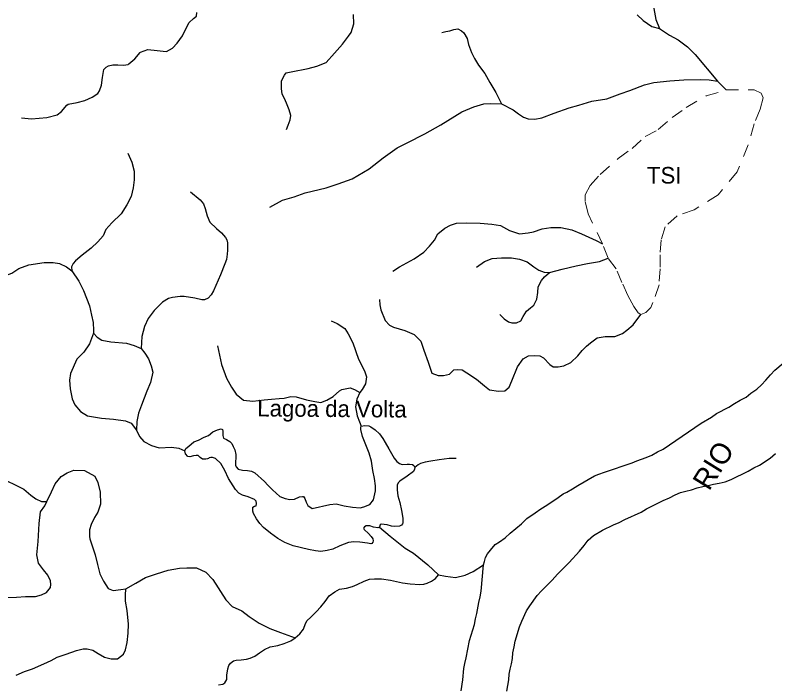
# Model space of a CAD drawing. Extents: x 436.3 to 500.4, y 8231 to 8286.4.
# Drawn here: x 478.01 to 485.33, y 8235.53 to 8241.98 of the extents above; entities that cross this region are included whole.
import ezdxf
from ezdxf.enums import TextEntityAlignment as Align

# ---------------------------------------------------------------- set-up
doc = ezdxf.new("R2010")
doc.units = 0
doc.header["$LTSCALE"] = 0.08
doc.linetypes.add('LONG_DASHED', pattern=[7.5, 6, -1.5])
doc.linetypes.add('SHORT_DASHED', pattern=[2.7, 1.5, -1.2])
for name, color, linetype, lineweight in [('2', 7, 'Continuous', 25), ('21', 7, 'SHORT_DASHED', 13), ('9', 7, 'LONG_DASHED', 25)]:
    doc.layers.add(name, color=color, linetype=linetype, lineweight=lineweight)
doc.layers.add('61', color=7, linetype='Continuous')

msp = doc.modelspace()

# ---------------------------------------------------------------- linework, layer by layer
at = {"layer": '2'}
msp.add_line((482.4993, 8236.4278), (482.5205, 8236.6809), dxfattribs=at)
for points in [[(482.5585, 8236.7874), (482.5884, 8236.8242), (482.6352, 8236.8765), (482.6757, 8236.9034), (482.7298, 8236.9437), (482.7794, 8236.9886), (482.8876, 8237.0783), (482.9373, 8237.1276), (483.0185, 8237.1814), (483.0726, 8237.2218), (483.1312, 8237.2577), (483.2395, 8237.3294), (483.2892, 8237.3653), (483.3252, 8237.3833), (483.3794, 8237.4146), (483.4291, 8237.446), (483.5916, 8237.5402), (483.6322, 8237.5537), (483.6863, 8237.5761), (483.9526, 8237.6657), (483.9978, 8237.6837), (484.0892, 8237.7158), (484.1423, 8237.7374), (484.1965, 8237.7688), (484.2508, 8237.7957), (484.6172, 8238.0473), (484.7168, 8238.1052), (484.7666, 8238.1411), (484.8842, 8238.1994), (484.9385, 8238.2353), (484.9928, 8238.2667), (485.0516, 8238.2981), (485.0969, 8238.3339), (485.1558, 8238.3743), (485.2011, 8238.4147), (485.2419, 8238.4596), (485.2872, 8238.5134), (485.328, 8238.5583), (485.4095, 8238.6256)], [(479.6433, 8237.7815), (479.6539, 8237.8026), (479.6832, 8237.8264), (479.7285, 8237.8659), (479.7736, 8237.8842), (479.8294, 8237.9105), (479.872, 8237.929), (479.9145, 8237.9631), (479.9571, 8237.9816), (479.9943, 8237.9921), (480.0075, 8237.9868), (480.0102, 8237.9682), (480.0082, 8237.9546), (480.0082, 8237.9415), (480.0105, 8237.9291), (480.0167, 8237.9006), (480.0444, 8237.8889), (480.0762, 8237.8704), (480.0947, 8237.8519), (480.1105, 8237.8228), (480.1237, 8237.791), (480.1342, 8237.7461), (480.1319, 8237.6433), (480.1372, 8237.6275), (480.1584, 8237.6036), (480.1981, 8237.593), (480.2485, 8237.5903), (480.2856, 8237.5849), (480.3175, 8237.569), (480.4108, 8237.4844), (480.4422, 8237.4485), (480.487, 8237.4036), (480.5588, 8237.3407), (480.6113, 8237.3202), (480.6536, 8237.3122), (480.7014, 8237.3147), (480.7491, 8237.3358), (480.7757, 8237.341), (480.7863, 8237.341), (480.7996, 8237.3199), (480.8127, 8237.2855), (480.8285, 8237.255), (480.8689, 8237.2236), (481.0399, 8237.2637), (481.1028, 8237.2681), (481.1792, 8237.2501), (481.2601, 8237.2365), (481.3321, 8237.232), (481.3681, 8237.2409), (481.4266, 8237.2633), (481.4627, 8237.3081), (481.4809, 8237.3933), (481.4811, 8237.4427), (481.4723, 8237.5145), (481.4545, 8237.5907), (481.4413, 8237.6805), (481.4191, 8237.7568), (481.3566, 8237.9183), (481.3408, 8237.9847), (481.3382, 8238.0031), (481.3435, 8238.019)], [(481.3435, 8238.019), (481.378, 8238.0242), (481.4178, 8238.0216), (481.4363, 8238.011), (481.4787, 8237.9819), (481.5184, 8237.9422), (481.55, 8237.8999), (481.5738, 8237.8603), (481.608, 8237.7994), (481.6608, 8237.7095), (481.6872, 8237.6778), (481.711, 8237.6592), (481.7375, 8237.6487), (481.7852, 8237.6513), (481.8091, 8237.6513), (481.8383, 8237.6486), (481.8515, 8237.638), (481.8594, 8237.6195)], [(481.4617, 8237.0442), (481.4272, 8237.0575), (481.3901, 8237.0575), (481.3742, 8237.0496), (481.3661, 8237.0364), (481.3714, 8237.0232), (481.4138, 8236.9834), (481.4402, 8236.9544), (481.456, 8236.9332), (481.4586, 8236.9121), (481.4559, 8236.8989), (481.4453, 8236.8883), (481.4347, 8236.8857), (481.4029, 8236.891), (481.3312, 8236.9), (481.2728, 8236.9046), (481.2188, 8236.8957), (481.1378, 8236.8644), (481.0703, 8236.8331), (481.0163, 8236.8197), (480.9533, 8236.8108), (480.9038, 8236.8154), (480.8364, 8236.8289), (480.6881, 8236.8651), (480.6072, 8236.8966), (480.5398, 8236.9371), (480.468, 8236.9865), (480.4006, 8237.0405), (480.3647, 8237.0809), (480.3333, 8237.1258), (480.3065, 8237.1752), (480.2971, 8237.1991), (480.2972, 8237.2255), (480.2999, 8237.236), (480.3159, 8237.2465), (480.3292, 8237.2518), (480.3345, 8237.2729), (480.3293, 8237.2941), (480.316, 8237.3099), (480.2551, 8237.3365), (480.1994, 8237.3524), (480.1623, 8237.371), (480.1305, 8237.4081), (480.0645, 8237.5138), (480.0276, 8237.5905), (479.9906, 8237.6593), (479.9377, 8237.7069), (479.9112, 8237.7149), (479.8926, 8237.715), (479.8767, 8237.7123), (479.8713, 8237.7071), (479.8633, 8237.7018), (479.8447, 8237.6992), (479.8129, 8237.6993), (479.7917, 8237.7152), (479.7705, 8237.7337), (479.752, 8237.7364), (479.7281, 8237.7312), (479.6908, 8237.7207), (479.6723, 8237.7261), (479.6485, 8237.7498), (479.6433, 8237.7815)], [(484.6331, 8237.4362), (484.6873, 8237.4452), (484.7371, 8237.4586), (484.7913, 8237.4675), (484.85, 8237.4809), (484.9088, 8237.5033), (485.0717, 8237.584), (485.126, 8237.6154), (485.1803, 8237.6423), (485.2845, 8237.7095), (485.3343, 8237.7544)], [(481.8594, 8237.6195), (481.8566, 8237.6036), (481.846, 8237.5825), (481.7871, 8237.5366), (481.715, 8237.4873), (481.6988, 8237.4721), (481.6881, 8237.4484), (481.688, 8237.4034), (481.6958, 8237.3453), (481.7142, 8237.2818), (481.7322, 8237.2047), (481.7455, 8237.1329), (481.7453, 8237.088), (481.7401, 8237.0783), (481.7295, 8237.0651), (481.7109, 8237.0545), (481.6684, 8237.052), (481.634, 8237.0546)], [(484.3123, 8237.3288), (484.3665, 8237.3557), (484.4207, 8237.3781), (484.4704, 8237.3915), (484.5247, 8237.4049), (484.5789, 8237.4228), (484.6331, 8237.4362)], [(482.746, 8235.4671), (482.764, 8235.5748), (482.7684, 8235.6287), (482.7774, 8235.678), (482.7909, 8235.7274), (482.7999, 8235.7813), (482.8044, 8235.8351), (482.818, 8235.8935), (482.827, 8235.9473), (482.8696, 8236.0843), (482.8901, 8236.1403), (482.9352, 8236.239), (482.9668, 8236.2884), (483.0389, 8236.387), (483.0795, 8236.4319), (483.1832, 8236.5351), (483.2328, 8236.5934), (483.3457, 8236.7055), (483.445, 8236.8132), (483.4902, 8236.867), (483.5309, 8236.9208), (483.5821, 8236.9651), (483.6663, 8237.015), (483.7747, 8237.0688), (483.8288, 8237.0912), (483.883, 8237.1181), (484.0409, 8237.1882), (484.0908, 8237.2212), (484.2535, 8237.3019), (484.3123, 8237.3288)], [(481.5199, 8237.0441), (481.504, 8237.0389), (481.4617, 8237.0442)], [(481.634, 8237.0546), (481.5942, 8237.0679), (481.536, 8237.0732), (481.5253, 8237.068), (481.5199, 8237.0441)], [(482.5205, 8236.6809), (482.5304, 8236.7134), (482.5306, 8236.7141), (482.5399, 8236.7531), (482.5585, 8236.7874)], [(482.3052, 8235.4675), (482.3232, 8235.5752), (482.3322, 8235.6829), (482.3412, 8235.7323), (482.3547, 8235.7861), (482.3872, 8235.9538), (482.4357, 8236.1076), (482.4449, 8236.163), (482.4585, 8236.2124), (482.4766, 8236.3201), (482.4902, 8236.3739), (482.4993, 8236.4278)]]:
    msp.add_lwpolyline(points, dxfattribs=at)
at = {"layer": '21'}
msp.add_line((483.7228, 8239.6353), (483.6676, 8239.7737), dxfattribs=at)
for points in [[(483.6676, 8239.7737), (483.5291, 8240.0628), (483.5003, 8240.1878), (483.5003, 8240.2455), (483.5485, 8240.3349), (483.6449, 8240.4407), (483.8183, 8240.5947), (483.9532, 8240.6908), (484.0785, 8240.8063), (484.2038, 8240.8737), (484.3387, 8240.989), (484.4735, 8241.0853), (484.6664, 8241.1979), (484.8593, 8241.2554)], [(484.8593, 8241.2554), (485.0716, 8241.255), (485.1295, 8241.2549), (485.1971, 8241.2259), (485.2164, 8241.1778), (485.1876, 8241.0718), (485.1298, 8240.9275), (485.072, 8240.7254), (484.9659, 8240.4657), (484.7825, 8240.2447), (484.5509, 8240.1007), (484.3868, 8240.0432), (484.271, 8239.9375), (484.2323, 8239.8125), (484.2224, 8239.6683), (484.2222, 8239.5338), (484.2123, 8239.38), (484.1541, 8239.2072), (484.1347, 8239.1592), (484.0864, 8239.1113), (484.0381, 8239.092)], [(484.0381, 8239.092), (484.0114, 8239.1076), (483.9708, 8239.1689), (483.9133, 8239.2746), (483.8557, 8239.3995), (483.7982, 8239.534), (483.7228, 8239.6353)]]:
    msp.add_lwpolyline(points, dxfattribs=at)
at = {"layer": '9'}
for points in [[(484.1215, 8242.3853), (484.1999, 8242.3364), (484.2104, 8242.2515), (484.1765, 8242.139), (484.1619, 8242.0411), (484.1817, 8241.9335), (484.2161, 8241.8455)], [(478.0685, 8240.986), (478.1651, 8240.9766), (478.3123, 8240.9899), (478.4134, 8241.0171), (478.4548, 8241.0491), (478.5053, 8241.1086), (478.5191, 8241.1177), (478.6065, 8241.1358), (478.6799, 8241.1539), (478.749, 8241.1858), (478.8041, 8241.2223), (478.8224, 8241.2452), (478.8407, 8241.3002), (478.8499, 8241.3736), (478.8635, 8241.4516), (478.8865, 8241.4745), (478.9094, 8241.4883), (478.9508, 8241.4973), (478.9967, 8241.4971), (479.0519, 8241.4924), (479.0979, 8241.5015), (479.1024, 8241.5061), (479.1622, 8241.5564), (479.2126, 8241.616), (479.2172, 8241.6205), (479.2861, 8241.6433), (479.3781, 8241.634), (479.4332, 8241.6293), (479.4653, 8241.6246), (479.525, 8241.6567), (479.5709, 8241.7071), (479.6224, 8241.7777), (479.65, 8241.8374), (479.6866, 8241.9062), (479.7278, 8241.9429), (479.7554, 8241.9658), (479.7599, 8242.0025)], [(480.6233, 8240.8748), (480.6393, 8240.915), (480.6594, 8240.9674), (480.6633, 8241.0077), (480.6472, 8241.0642), (480.631, 8241.1126), (480.6067, 8241.165), (480.5826, 8241.2133), (480.5744, 8241.2698), (480.5743, 8241.3424), (480.6024, 8241.3988), (480.6185, 8241.419), (480.6669, 8241.4311), (480.8319, 8241.4634), (480.9165, 8241.4836), (481.005, 8241.5199), (481.0853, 8241.6087), (481.1618, 8241.6974), (481.2194, 8241.7719), (481.2475, 8241.8083), (481.2716, 8241.893), (481.2675, 8241.9817)], [(484.0022, 8241.9802), (484.0588, 8241.9236), (484.1437, 8241.8671), (484.2161, 8241.8455)], [(482.121, 8241.8086), (482.1597, 8241.8184), (482.1982, 8241.8256), (482.2369, 8241.8378), (482.2732, 8241.8427), (482.3094, 8241.8234), (482.3312, 8241.8065), (482.3627, 8241.7508), (482.3773, 8241.6927), (482.4064, 8241.6152), (482.4354, 8241.5572), (482.4718, 8241.4943), (482.5347, 8241.4145), (482.5832, 8241.3274), (482.6413, 8241.2306), (482.6949, 8241.1213)], [(484.2161, 8241.8455), (484.3141, 8241.7818), (484.3974, 8241.7377), (484.4856, 8241.6691), (484.5592, 8241.5956), (484.7758, 8241.3396), (484.8593, 8241.2554)], [(482.6949, 8241.1213), (482.8062, 8241.0636), (482.8598, 8241.0266), (482.9051, 8240.9936), (482.9505, 8240.9771), (483.0165, 8240.973), (483.0824, 8240.9855), (483.202, 8241.0309), (483.3461, 8241.0845), (483.441, 8241.1093), (483.5648, 8241.1465), (483.7092, 8241.1712), (483.837, 8241.2166), (483.9319, 8241.2496), (484.0722, 8241.3032), (484.163, 8241.3279), (484.3157, 8241.3443), (484.4521, 8241.3524), (484.6104, 8241.3563), (484.6944, 8241.3534), (484.7758, 8241.3396)], [(480.4635, 8240.1272), (480.5841, 8240.1928), (480.6983, 8240.2258), (480.8041, 8240.2642), (481.0058, 8240.3124), (481.1211, 8240.3509), (481.2557, 8240.3991), (481.419, 8240.4954), (481.5535, 8240.6013), (481.688, 8240.6977), (481.7841, 8240.7459), (481.9571, 8240.8326), (482.1108, 8240.9194), (482.3126, 8241.0448), (482.428, 8241.093), (482.5241, 8241.122), (482.5919, 8241.1253), (482.6949, 8241.1213)], [(479.0944, 8240.6464), (479.1312, 8240.5593), (479.1542, 8240.4724), (479.1542, 8240.3899), (479.1451, 8240.3122), (479.1268, 8240.23), (479.0854, 8240.1477), (479.0303, 8240.061), (478.9384, 8239.9745), (478.8834, 8239.9107), (478.8558, 8239.8515), (478.8053, 8239.7922), (478.741, 8239.733), (478.6537, 8239.6648), (478.5894, 8239.6103), (478.5664, 8239.5829), (478.5525, 8239.551), (478.5537, 8239.5131)], [(479.6975, 8240.274), (479.791, 8240.1961), (479.8222, 8240.1571), (479.8395, 8240.1149), (479.8582, 8240.0418), (479.8836, 8239.9807), (479.9498, 8239.9196), (479.9976, 8239.8783), (480.0347, 8239.8341), (480.0471, 8239.8111), (480.0542, 8239.7828), (480.0541, 8239.7475), (480.054, 8239.7121), (480.0522, 8239.6733), (480.0433, 8239.6239), (480.029, 8239.5816), (479.9862, 8239.4756), (479.9416, 8239.3726), (479.9185, 8239.3215), (479.8971, 8239.2827), (479.867, 8239.2503), (479.8313, 8239.2352), (479.8058, 8239.2352), (479.7397, 8239.2505), (479.6379, 8239.266), (479.5971, 8239.2661), (479.5258, 8239.2562), (479.485, 8239.2461), (479.4289, 8239.2108), (479.3523, 8239.135), (479.3471, 8239.13), (479.291, 8239.0541), (479.2551, 8238.9782), (479.2295, 8238.882), (479.2233, 8238.7645)], [(481.6461, 8239.5103), (481.7108, 8239.5518), (481.8538, 8239.6302), (481.9461, 8239.6947), (482.0016, 8239.75), (482.0477, 8239.81), (482.0801, 8239.8699), (482.1493, 8239.9253), (482.2046, 8239.953), (482.26, 8239.9715), (482.3569, 8239.9761), (482.4906, 8239.9716), (482.6013, 8239.9625), (482.6843, 8239.9487), (482.772, 8239.9026), (482.8689, 8239.8704), (482.9519, 8239.8797), (483.0026, 8239.8889), (483.0858, 8239.9166), (483.1689, 8239.9304), (483.2659, 8239.9304), (483.3721, 8239.9074), (483.4644, 8239.8705), (483.6076, 8239.8059), (483.6676, 8239.7737)], [(477.4125, 8239.4468), (477.444, 8239.4481), (477.4805, 8239.4535), (477.5518, 8239.473), (477.6548, 8239.4806), (477.726, 8239.4765), (477.7893, 8239.4526), (477.8884, 8239.4602), (477.9755, 8239.4915), (478.0429, 8239.5346), (478.1418, 8239.5697), (478.2884, 8239.5929), (478.3755, 8239.5926), (478.435, 8239.5845), (478.5023, 8239.5527), (478.5537, 8239.5131)], [(482.4531, 8239.5476), (482.5316, 8239.6029), (482.6055, 8239.6306), (482.6932, 8239.6398), (482.79, 8239.6399), (482.8685, 8239.6261), (482.9423, 8239.5985), (483.0068, 8239.5524), (483.0529, 8239.5201), (483.1054, 8239.5003), (483.1561, 8239.4988)], [(483.1561, 8239.4988), (483.2791, 8239.5293), (483.4131, 8239.5616), (483.524, 8239.5846), (483.6396, 8239.6031), (483.7228, 8239.6353)], [(478.5537, 8239.5131), (478.6209, 8239.4144), (478.6683, 8239.3236), (478.7234, 8239.1778), (478.7452, 8239.0855), (478.7609, 8239.0146), (478.7647, 8238.9398), (478.7639, 8238.9123)], [(482.6782, 8239.0916), (482.7196, 8239.0502), (482.7611, 8239.0226), (482.7933, 8239.0134), (482.8395, 8239.0134), (482.8811, 8239.0318), (482.9043, 8239.0732), (482.9367, 8239.1239), (482.9737, 8239.1562), (483.0061, 8239.1838), (483.0338, 8239.2391), (483.0433, 8239.3035), (483.048, 8239.3588), (483.0804, 8239.4187), (483.1081, 8239.4556), (483.1561, 8239.4988)], [(481.5177, 8239.2359), (481.5223, 8239.1846), (481.5315, 8239.1379), (481.5733, 8239.0354), (481.6151, 8238.9888), (481.6524, 8238.9701), (481.7645, 8238.9375), (481.8532, 8238.9003), (481.9184, 8238.835), (481.9462, 8238.751), (481.9879, 8238.6345), (482.0249, 8238.5273), (482.0856, 8238.504), (482.137, 8238.504), (482.1931, 8238.518), (482.2353, 8238.5599), (482.268, 8238.5646), (482.3148, 8238.5599), (482.3614, 8238.532), (482.4547, 8238.4714), (482.5293, 8238.4061), (482.5805, 8238.3688), (482.6647, 8238.3547), (482.7254, 8238.3593), (482.7676, 8238.3919), (482.7958, 8238.4525), (482.8477, 8238.5878), (482.9041, 8238.667), (482.9556, 8238.695), (483.0164, 8238.6996), (483.0631, 8238.695), (483.1005, 8238.6763), (483.1612, 8238.611), (483.1938, 8238.5877), (483.2406, 8238.5877), (483.2967, 8238.597), (483.3624, 8238.6296), (483.4295, 8238.6951), (483.4718, 8238.7465), (483.5141, 8238.7884), (483.5516, 8238.8211), (483.6172, 8238.8677), (483.6922, 8238.8816), (483.7864, 8238.8818), (483.8615, 8238.9097), (483.9037, 8238.9424), (483.9648, 8238.9937), (484.0381, 8239.092)], [(481.0525, 8239.0322), (481.1107, 8239.0057), (481.1846, 8238.9582), (481.2162, 8238.9054), (481.2636, 8238.8209), (481.3161, 8238.6624), (481.3741, 8238.5515), (481.3951, 8238.4934), (481.3843, 8238.4247), (481.3523, 8238.3719), (481.331, 8238.3403)], [(478.7639, 8238.9123), (478.7241, 8238.8091), (478.6707, 8238.7299), (478.6015, 8238.6615), (478.5428, 8238.5243), (478.5319, 8238.4609), (478.5371, 8238.3763), (478.5581, 8238.2812), (478.5845, 8238.223), (478.6376, 8238.1594), (478.7065, 8238.1168), (478.8394, 8238.0953), (478.9562, 8238.0844), (479.0731, 8238.0682), (479.1262, 8238.0469), (479.1778, 8237.9805)], [(478.7639, 8238.9123), (478.7986, 8238.8749), (478.8436, 8238.845), (478.9307, 8238.8291), (479.0811, 8238.8168), (479.1562, 8238.7929), (479.2233, 8238.7645)], [(479.9573, 8238.7897), (479.9969, 8238.6109), (480.0443, 8238.4789), (480.0917, 8238.3944), (480.1392, 8238.3257), (480.2079, 8238.2675), (480.298, 8238.2569), (480.4092, 8238.2725), (480.4781, 8238.2776), (480.5523, 8238.2828), (480.6, 8238.2881), (480.6636, 8238.3038), (480.7166, 8238.2985), (480.8172, 8238.272), (480.8966, 8238.2561), (480.9548, 8238.2455), (481.0131, 8238.2665), (481.0715, 8238.3035), (481.1351, 8238.3562), (481.1564, 8238.372), (481.2359, 8238.3878), (481.2782, 8238.3719), (481.331, 8238.3403)], [(479.2233, 8238.7645), (479.2589, 8238.7218), (479.2943, 8238.6667), (479.3178, 8238.5989), (479.3336, 8238.5367), (479.3135, 8238.4385), (479.2776, 8238.356), (479.2259, 8238.2198), (479.1979, 8238.1413), (479.1819, 8238.0627), (479.1778, 8237.9805)], [(481.331, 8238.3403), (481.2991, 8238.2769), (481.2882, 8238.203), (481.3039, 8238.1185), (481.3249, 8238.0605), (481.3435, 8238.019)], [(479.1778, 8237.9805), (479.2052, 8237.917), (479.2486, 8237.8702), (479.3236, 8237.8302), (479.3947, 8237.8104), (479.5134, 8237.814), (479.5845, 8237.8059), (479.6433, 8237.7815)], [(477.2946, 8237.4658), (477.3621, 8237.4868), (477.3975, 8237.4973), (477.4758, 8237.5183), (477.4971, 8237.5288), (477.5184, 8237.5605), (477.5256, 8237.6063), (477.5364, 8237.6522), (477.5542, 8237.6769), (477.5719, 8237.691), (477.6003, 8237.6909), (477.643, 8237.6837), (477.6926, 8237.6623), (477.7352, 8237.634), (477.7955, 8237.5844), (477.8451, 8237.5349), (477.9232, 8237.4958), (478.0154, 8237.4497), (478.0934, 8237.4106), (478.1608, 8237.3539), (478.2069, 8237.3184), (478.2637, 8237.2936), (478.3133, 8237.2934)], [(482.2566, 8237.7048), (482.19, 8237.7049), (482.0942, 8237.6943), (482.0143, 8237.6811), (481.9583, 8237.6705), (481.9157, 8237.6572), (481.8916, 8237.644), (481.8594, 8237.6195)], [(478.3133, 8237.2934), (478.3593, 8237.384), (478.3931, 8237.4619), (478.453, 8237.5324), (478.5092, 8237.5694), (478.5728, 8237.5952), (478.6775, 8237.5911), (478.7746, 8237.535), (478.8043, 8237.4755), (478.8265, 8237.3825), (478.83, 8237.2673), (478.8036, 8237.1893), (478.7737, 8237.1374), (478.7399, 8237.0706), (478.7249, 8237.0206), (478.7248, 8236.9536), (478.7284, 8236.9314), (478.7805, 8236.7788), (478.8027, 8236.6858), (478.825, 8236.5965), (478.8585, 8236.5258), (478.9032, 8236.455), (478.9518, 8236.4363), (479.0265, 8236.4434), (479.0736, 8236.4512)], [(477.8845, 8236.3682), (478.0229, 8236.3715), (478.1089, 8236.3787), (478.206, 8236.3784), (478.2621, 8236.3931), (478.3107, 8236.4152), (478.3482, 8236.4635), (478.3519, 8236.4932), (478.3483, 8236.5267), (478.3221, 8236.5825), (478.2812, 8236.6346), (478.2326, 8236.6981), (478.2179, 8236.7798), (478.2293, 8236.9062), (478.2408, 8237.0809), (478.2542, 8237.1911), (478.2954, 8237.2504), (478.3133, 8237.2934)], [(481.5199, 8237.0441), (481.6217, 8236.9569), (481.7661, 8236.8439), (481.8478, 8236.7936), (481.9861, 8236.6806), (482.0882, 8236.5871)], [(479.0736, 8236.4512), (479.1724, 8236.5062), (479.2658, 8236.5617), (479.3705, 8236.5949), (479.4826, 8236.6318), (479.591, 8236.65), (479.6619, 8236.6535), (479.7553, 8236.6533), (479.8448, 8236.6122), (479.9119, 8236.5414), (480.0386, 8236.344), (480.0983, 8236.2807), (480.1933, 8236.2385), (480.2641, 8236.1862), (480.3611, 8236.1191), (480.4618, 8236.0705), (480.5663, 8236.0294), (480.707, 8235.9789)], [(482.0882, 8236.5871), (482.1557, 8236.5737), (482.2516, 8236.5613), (482.3445, 8236.5827), (482.4201, 8236.6175), (482.5205, 8236.6809)], [(480.707, 8235.9789), (480.7522, 8236.018), (480.7858, 8236.0639), (480.8075, 8236.1167), (480.8232, 8236.146), (480.8527, 8236.1754), (480.9077, 8236.2281), (480.955, 8236.2789), (480.9943, 8236.3278), (481.0357, 8236.3844), (481.0874, 8236.4219), (481.1345, 8236.4473), (481.2013, 8236.4589), (481.2603, 8236.4726), (481.3055, 8236.4921), (481.3723, 8236.5233), (481.4234, 8236.5428), (481.4705, 8236.5486), (481.5392, 8236.5485), (481.6236, 8236.5348), (481.7394, 8236.5092), (481.8132, 8236.4992), (481.9074, 8236.4913), (481.9447, 8236.4971), (481.9781, 8236.5069), (482.0193, 8236.5245), (482.0586, 8236.5499), (482.0882, 8236.5871)], [(478.0172, 8235.6206), (478.0976, 8235.6556), (478.1748, 8235.681), (478.2841, 8235.7286), (478.3549, 8235.7605), (478.4127, 8235.7923), (478.4995, 8235.8209), (478.5992, 8235.8558), (478.6635, 8235.8747), (478.7021, 8235.8746), (478.7567, 8235.8617), (478.8081, 8235.8295), (478.8691, 8235.7941), (478.9334, 8235.778), (478.9945, 8235.7778), (479.0523, 8235.8224), (479.0717, 8235.8639), (479.0878, 8235.9343), (479.0976, 8236.0238), (479.1009, 8236.1102), (479.0881, 8236.2414), (479.0702, 8236.3328), (479.0703, 8236.3905), (479.0736, 8236.4512)], [(479.9665, 8235.5268), (480.0081, 8235.5314), (480.0278, 8235.5451), (480.0475, 8235.5783), (480.0495, 8235.6194), (480.0574, 8235.682), (480.0672, 8235.7133), (480.0849, 8235.7348), (480.1125, 8235.7563), (480.138, 8235.7641), (480.1872, 8235.7679), (480.2382, 8235.7737), (480.2735, 8235.7833), (480.3187, 8235.8028), (480.364, 8235.834), (480.4123, 8235.866), (480.4653, 8235.8913), (480.54, 8235.9068), (480.6009, 8235.9243), (480.6637, 8235.9497), (480.707, 8235.9789)]]:
    msp.add_lwpolyline(points, dxfattribs=at)

# ---------------------------------------------------------------- texts
at = {"layer": '61'}
for s, rotation, p in [('RIO                                    JEQUITINHONHA', 58.212, (486.1003, 8239.6531)), ('Córrego                                 Fino', 33.776, (486.18, 8235.8288))]:
    msp.add_text(s, height=0.2, rotation=rotation, dxfattribs=at).set_placement(p, align=Align.CENTER)
msp.add_text('TSI', height=0.16, dxfattribs=at).set_placement((484.2625, 8240.3535), align=Align.CENTER)
msp.add_text('Lagoa da Volta', height=0.16, rotation=359.571, dxfattribs=at).set_placement((481.7803, 8238.1005), align=Align.RIGHT)

doc.saveas('drawing.dxf')
